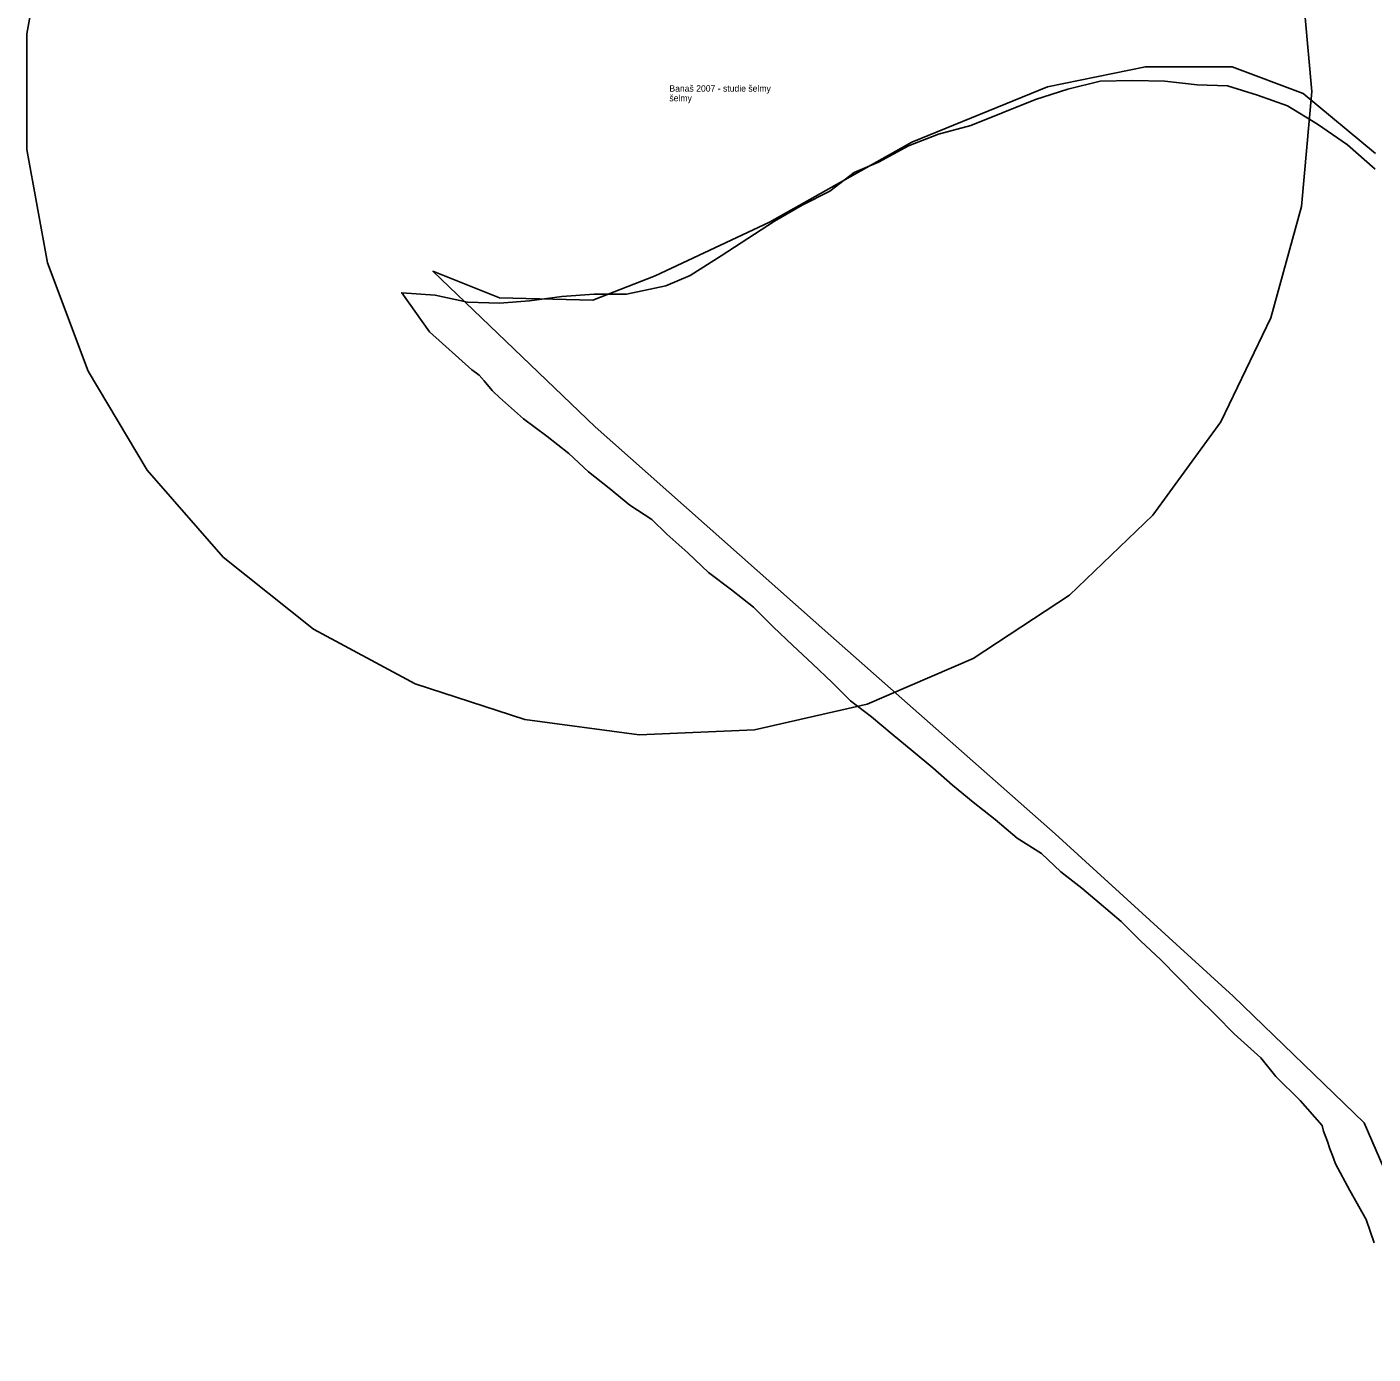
# Model space of a CAD drawing. Extents: x -477403 to -465463, y -1159182 to -1149227.
# Drawn here: x -468485.6 to -468067.4, y -1155016.4 to -1154604.2 of the extents above; entities that cross this region are included whole.
import ezdxf

# ---------------------------------------------------------------- set-up
doc = ezdxf.new("R2010")
doc.units = 0
for name, color, linetype in [('Vrstva 1', 7, 'Continuous'), ('Vrstva 10_stav', 7, 'Continuous'), ('Vrstva 2', 7, 'Continuous')]:
    doc.layers.add(name, color=color, linetype=linetype)

msp = doc.modelspace()

# ---------------------------------------------------------------- linework, layer by layer
at = {"layer": 'Vrstva 10_stav'}
for points in [[(-468089.615, -1154588.546), (-468086.401, -1154624.257), (-468089.615, -1154659.969), (-468099.154, -1154694.532), (-468114.711, -1154726.837), (-468135.787, -1154755.845), (-468161.703, -1154780.624), (-468191.627, -1154800.376), (-468224.598, -1154814.469), (-468259.554, -1154822.447), (-468295.374, -1154824.056), (-468330.905, -1154819.243), (-468365.006, -1154808.163), (-468396.58, -1154791.172), (-468424.614, -1154768.816), (-468448.204, -1154741.814), (-468466.595, -1154711.034), (-468479.194, -1154677.465), (-468485.596, -1154642.185), (-468485.596, -1154606.329), (-468479.194, -1154571.05)], [(-468039.029, -1155016.384), (-468070.107, -1154944.558), (-468110.854, -1154905.193), (-468166.104, -1154854.777), (-468235.857, -1154793.311), (-468309.064, -1154728.392), (-468359.48, -1154680.048), (-468338.761, -1154688.336), (-468309.755, -1154689.026), (-468290.417, -1154681.429), (-468254.85, -1154664.854), (-468210.65, -1154639.992), (-468168.521, -1154622.726), (-468138.134, -1154616.51), (-468111.199, -1154616.51), (-468089.099, -1154624.798), (-468066.654, -1154643.445)], [(-468039.029, -1155016.384), (-468070.107, -1154944.558), (-468110.854, -1154905.193), (-468166.104, -1154854.777), (-468235.858, -1154793.311), (-468309.064, -1154728.392), (-468359.48, -1154680.048), (-468338.761, -1154688.336), (-468309.755, -1154689.026), (-468290.417, -1154681.429), (-468254.85, -1154664.854), (-468210.65, -1154639.992), (-468168.521, -1154622.726), (-468138.134, -1154616.51), (-468111.199, -1154616.51), (-468089.099, -1154624.798), (-468066.654, -1154643.445)], [(-468039.029, -1155016.384), (-468070.107, -1154944.558), (-468110.854, -1154905.193), (-468166.104, -1154854.777), (-468235.858, -1154793.311), (-468309.064, -1154728.392), (-468359.48, -1154680.048), (-468338.761, -1154688.336), (-468309.755, -1154689.026), (-468290.417, -1154681.429), (-468254.85, -1154664.854), (-468210.65, -1154639.992), (-468168.521, -1154622.726), (-468138.134, -1154616.51), (-468111.199, -1154616.51), (-468089.099, -1154624.798), (-468066.654, -1154643.445)], [(-468039.029, -1155016.384), (-468070.107, -1154944.558), (-468110.854, -1154905.193), (-468166.104, -1154854.777), (-468235.858, -1154793.311), (-468309.064, -1154728.392), (-468359.48, -1154680.048), (-468338.761, -1154688.336), (-468309.755, -1154689.026), (-468290.417, -1154681.429), (-468254.85, -1154664.854), (-468210.65, -1154639.992), (-468168.521, -1154622.726), (-468138.134, -1154616.51), (-468111.199, -1154616.51), (-468089.099, -1154624.798), (-468066.654, -1154643.445)], [(-468039.029, -1155016.384), (-468070.107, -1154944.558), (-468110.854, -1154905.193), (-468166.104, -1154854.777), (-468235.858, -1154793.311), (-468309.064, -1154728.392), (-468359.48, -1154680.048), (-468338.761, -1154688.336), (-468309.755, -1154689.026), (-468290.417, -1154681.429), (-468254.85, -1154664.854), (-468210.65, -1154639.992), (-468168.521, -1154622.726), (-468138.134, -1154616.51), (-468111.199, -1154616.51), (-468089.099, -1154624.798), (-468066.654, -1154643.445)], [(-468192.344, -1154634.75), (-468182.281, -1154630.75), (-468172.25, -1154626.75), (-468162.188, -1154623.5), (-468152.125, -1154621), (-468142.094, -1154620.75), (-468132.031, -1154621), (-468122, -1154622.125), (-468112.656, -1154622.5), (-468103.312, -1154625.375), (-468093.969, -1154628.625), (-468084.656, -1154634.375), (-468075.312, -1154640.75), (-468066.688, -1154648.375)], [(-468067.062, -1154981.875), (-468069.562, -1154974.625), (-468074.594, -1154965.625), (-468079.094, -1154957.25), (-468079.969, -1154954.75), (-468080.781, -1154952.625), (-468081.594, -1154950.375), (-468082.75, -1154947.125), (-468083.219, -1154945.375), (-468090.031, -1154937.625), (-468097.562, -1154930.125), (-468102.25, -1154924.375), (-468110.5, -1154916.875), (-468116.25, -1154911.125), (-468122, -1154905.375), (-468127.719, -1154899.625), (-468133.469, -1154893.875), (-468139.562, -1154888.125), (-468145.688, -1154882), (-468152.5, -1154876.25), (-468157.875, -1154871.625), (-468164.344, -1154866.625), (-468170.438, -1154860.875), (-468178, -1154856.125), (-468184.812, -1154850.375), (-468191.625, -1154845), (-468198.094, -1154839.625), (-468204.188, -1154834.25), (-468210.281, -1154829.25), (-468216.75, -1154823.875), (-468223.219, -1154818.5), (-468229.688, -1154813.5), (-468235.438, -1154807.75), (-468241.531, -1154802), (-468247.625, -1154796.25), (-468253.719, -1154790.5), (-468259.844, -1154784.375), (-468266.656, -1154779), (-468273.844, -1154773.625), (-468280.281, -1154767.5), (-468286.75, -1154761.75), (-468291.438, -1154757.125), (-468298.25, -1154752.75), (-468304.719, -1154747.375), (-468311.156, -1154742.375), (-468317.281, -1154736.625), (-468324.094, -1154731.25), (-468331.281, -1154725.875), (-468338.812, -1154719.25), (-468339.344, -1154718.75), (-468340.188, -1154717.875), (-468341.062, -1154717.125), (-468343.594, -1154714.125), (-468345.094, -1154712.375), (-468345.938, -1154711.75), (-468347.344, -1154710.625), (-468360.5, -1154698.875), (-468369.156, -1154686.75), (-468358.781, -1154687.5), (-468348.719, -1154689.625), (-468338.812, -1154690), (-468329.469, -1154689.25), (-468319.438, -1154687.875), (-468309.375, -1154687.125), (-468299.312, -1154687.125), (-468287.125, -1154684.625), (-468279.594, -1154681.375), (-468269.875, -1154675.25), (-468261.625, -1154669.875), (-468253.375, -1154664.5), (-468244.75, -1154659.5), (-468236.156, -1154655.125), (-468228.594, -1154649.375), (-468221.062, -1154646.125), (-468211.719, -1154641.125), (-468202.406, -1154637.5), (-468192.344, -1154634.75)]]:
    msp.add_lwpolyline(points, dxfattribs=at)

# ---------------------------------------------------------------- texts
at = {"layer": 'Vrstva 1'}
msp.add_text('šelmy', height=2, dxfattribs=at).set_placement((-468285.999, -1154627.257))
msp.add_text('šelmy', height=2, dxfattribs=at).set_placement((-468285.999, -1154627.257))
at = {"layer": 'Vrstva 2'}
msp.add_text('Banaš 2007 - studie šelmy', height=2, dxfattribs=at).set_placement((-468285.999, -1154624.257))
msp.add_text('Banaš 2007 - studie šelmy', height=2, dxfattribs=at).set_placement((-468285.999, -1154624.257))

doc.saveas('drawing.dxf')
